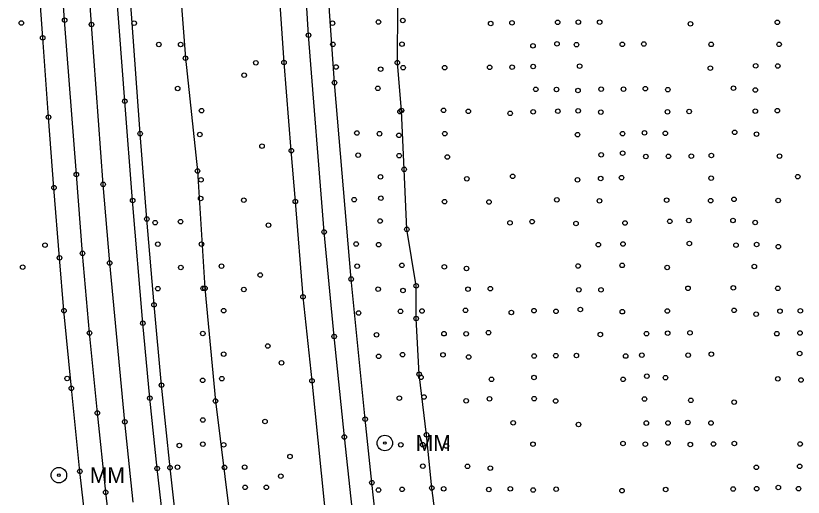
# Model space of a CAD drawing. Extents: x 20503438 to 20508873, y 7964251 to 7984667.
# Drawn here: x 20505414.7 to 20505763.9, y 7977994.1 to 7978207.5 of the extents above; entities that cross this region are included whole.
import ezdxf

# ---------------------------------------------------------------- set-up
doc = ezdxf.new("R2010")
doc.units = 0
for name, color, linetype in [('SurBreakLine', 7, 'Continuous'), ('SurDrainageArrowUp', 7, 'Continuous'), ('SurEdgeRoadPaved', 7, 'Continuous'), ('SurEdgeShoulderPaved', 7, 'Continuous'), ('SurRoadPoints', 7, 'Continuous'), ('SurSurveyPoints', 7, 'Continuous')]:
    doc.layers.add(name, color=color, linetype=linetype)

msp = doc.modelspace()

# ---------------------------------------------------------------- linework, layer by layer
at = {"layer": 'SurBreakLine'}
for points in [[(20505552.87, 7977978.47), (20505546.05, 7978045.7), (20505542.06, 7978082.94), (20505538.66, 7978125.24), (20505536.87, 7978147.75), (20505533.64, 7978186.84), (20505531.3, 7978221.22), (20505529.21, 7978255.03), (20505525.72, 7978323.37), (20505522.4, 7978394.4), (20505521.1, 7978429.03), (20505519.75, 7978458.72), (20505518.73, 7978501.89), (20505518.06, 7978531.07), (20505517.2, 7978583.22), (20505516.23, 7978653.48), (20505516.64, 7978710.22), (20505516.01, 7978735.22), (20505514.78, 7978760.21), (20505514.35, 7978785.2), (20505514.46, 7978817.7)], [(20505466.7, 7977991.92), (20505463.05, 7978027.55), (20505456.33, 7978097.95), (20505453.46, 7978132.8), (20505448.25, 7978203.68), (20505445.78, 7978239.4), (20505443.04, 7978273.69), (20505437.22, 7978404.79), (20505435.97, 7978443.35), (20505435.15, 7978478.03), (20505432.45, 7978640.01), (20505431.71, 7978709.45), (20505431.58, 7978734.45), (20505430.86, 7978759.44), (20505430.93, 7978784.44), (20505430.5, 7978796.56)]]:
    msp.add_lwpolyline(points, dxfattribs=at)
at = {"layer": 'SurDrainageArrowUp'}
for points in [[(20505602.24, 7977974.48), (20505599.16, 7977998.23), (20505596.82, 7978021.77), (20505593.55, 7978048.65), (20505592.23, 7978073.31), (20505592.27, 7978087.79), (20505588.1, 7978112.9), (20505586.91, 7978139.46), (20505585.7, 7978165.54), (20505583.91, 7978186.74), (20505584.15, 7978212.07), (20505581.05, 7978236.78), (20505581.32, 7978280.92), (20505580.84, 7978306.07), (20505580.17, 7978331.58), (20505581.09, 7978356.03), (20505579.49, 7978380.22), (20505579.69, 7978403.05), (20505578.72, 7978427.74)], [(20505474.88, 7978262.46), (20505478.99, 7978261.36), (20505482.21, 7978256.52), (20505486.17, 7978242.38), (20505487.91, 7978215.78), (20505489.93, 7978188.71), (20505495.31, 7978138.74), (20505498.58, 7978086.73), (20505503.22, 7978036.77), (20505509.44, 7977986.63), (20505514.32, 7977937.98), (20505520.92, 7977890), (20505527.82, 7977841.73), (20505542.62, 7977744.41), (20505553.31, 7977670.21)]]:
    msp.add_lwpolyline(points, dxfattribs=at)
at = {"layer": 'SurEdgeRoadPaved'}
for points in [[(20505566.3, 7977965.9), (20505560.41, 7978020.83), (20505555.87, 7978065.38), (20505551.42, 7978111.71), (20505544.52, 7978198.95), (20505542.7, 7978228.03), (20505541.09, 7978258.93), (20505537.75, 7978313.23), (20505535.28, 7978370.22), (20505534.58, 7978398.47), (20505532.2, 7978452.12), (20505531.93, 7978463.46), (20505530.96, 7978505.02), (20505530.55, 7978531.59), (20505528.81, 7978607.5), (20505527.04, 7978710.32), (20505526.81, 7978735.32), (20505526.38, 7978760.31), (20505526.15, 7978785.31), (20505524.78, 7978963.79)], [(20505463.18, 7977920.65), (20505454.58, 7977996.31), (20505450.89, 7978031.46), (20505447.41, 7978066.92), (20505444.29, 7978102.21), (20505441.55, 7978137.15), (20505436.35, 7978205.55), (20505433.64, 7978243.47), (20505431.53, 7978275.3), (20505426.62, 7978379.16), (20505424.19, 7978443.31), (20505423.37, 7978477.17), (20505421.86, 7978573.74), (20505421.02, 7978610.89), (20505420.15, 7978671.98), (20505420.51, 7978709.3), (20505420.18, 7978734.3), (20505419.46, 7978759.29), (20505419.53, 7978784.3), (20505418.19, 7978836.37)], [(20505484.78, 7977942.17), (20505477.37, 7978006.84), (20505474.16, 7978038.05), (20505471.02, 7978071.25), (20505466.52, 7978125.62), (20505463.03, 7978169.65), (20505458.22, 7978233.87), (20505456.38, 7978261.7), (20505452.65, 7978331.42), (20505449.66, 7978395.61), (20505448.48, 7978428.35), (20505447.47, 7978464.74), (20505446.76, 7978498.61), (20505444.84, 7978603.27), (20505443.98, 7978671.39), (20505443.11, 7978709.6), (20505442.78, 7978734.59), (20505442.86, 7978759.6), (20505442.33, 7978784.59), (20505442.48, 7978812.32)]]:
    msp.add_lwpolyline(points, dxfattribs=at)
at = {"layer": 'SurEdgeShoulderPaved'}
for points in [[(20505576.26, 7977966.69), (20505572.62, 7978000.58), (20505569.66, 7978028.71), (20505563.41, 7978090.82), (20505556.03, 7978177.85), (20505553.77, 7978209.53), (20505550.55, 7978266.31), (20505548.09, 7978306.49), (20505546.4, 7978339.91), (20505545.18, 7978373.07), (20505543.7, 7978404.19), (20505541.19, 7978469.47), (20505540.34, 7978515.04), (20505539.62, 7978564.96), (20505538.97, 7978593.38), (20505538.5, 7978624.24), (20505538.02, 7978682.14), (20505537.78, 7978710.42), (20505537.52, 7978735.42), (20505537.14, 7978760.41), (20505537.01, 7978785.41), (20505536.59, 7978812.4)], [(20505486.93, 7977972.52), (20505483.11, 7978007.2), (20505479.29, 7978043.79), (20505475.99, 7978079.42), (20505472.82, 7978117.44), (20505469.87, 7978155.29), (20505462.19, 7978261.58), (20505458.76, 7978328.16), (20505455.59, 7978394), (20505454.25, 7978428.29), (20505453.33, 7978459.97), (20505451.73, 7978529.85), (20505451.25, 7978561.06), (20505450.65, 7978609.09), (20505449.7, 7978709.68), (20505449.58, 7978734.68), (20505448.86, 7978759.68), (20505448.73, 7978784.68), (20505448.43, 7978797.39)], [(20505450.99, 7977936.46), (20505443.13, 7978005.6), (20505439.35, 7978042.41), (20505436.05, 7978076.83), (20505434.09, 7978100.23), (20505431.61, 7978131.31), (20505429.24, 7978162.59), (20505426.65, 7978197.75), (20505425.16, 7978218.23), (20505422.3, 7978254.13), (20505421.45, 7978269.03), (20505420.26, 7978289.89), (20505414.68, 7978424.62)]]:
    msp.add_lwpolyline(points, dxfattribs=at)
at = {"layer": 'SurRoadPoints'}
for centre, radius in [((20505578.33, 7978018.15), 3.43), ((20505578.33, 7978018.15), 0.571), ((20505433.81, 7978003.9), 3.43), ((20505433.81, 7978003.9), 0.571)]:
    msp.add_circle(centre, radius, dxfattribs=at)
at = {"layer": 'SurSurveyPoints'}
for centre in [(20505436.35, 7978205.55), (20505575.5, 7978204.77), (20505586.3, 7978205.46), (20505654.99, 7978204.61), (20505664.16, 7978204.72), (20505673.62, 7978204.66), (20505752.4, 7978204.63), (20505417.16, 7978204.34), (20505448.25, 7978203.68), (20505467.18, 7978204.24), (20505555.13, 7978204.23), (20505625.31, 7978204.07), (20505634.72, 7978204.39), (20505713.87, 7978203.95), (20505426.65, 7978197.75), (20505544.52, 7978198.95), (20505478.11, 7978194.82), (20505487.81, 7978194.82), (20505555.32, 7978194.87), (20505585.96, 7978194.97), (20505644.07, 7978194.24), (20505654.71, 7978195.09), (20505663.34, 7978194.73), (20505683.63, 7978194.85), (20505693.19, 7978195.01), (20505723.06, 7978194.84), (20505753.19, 7978194.89), (20505489.93, 7978188.71), (20505521.13, 7978186.71), (20505533.64, 7978186.84), (20505556.74, 7978184.84), (20505576.48, 7978183.84), (20505583.91, 7978186.74), (20505586.46, 7978184.5), (20505604.91, 7978184.53), (20505624.85, 7978184.66), (20505634.78, 7978184.74), (20505644.13, 7978185.02), (20505664.71, 7978185.19), (20505722.71, 7978184.3), (20505742.82, 7978185.33), (20505752.58, 7978185.27), (20505515.97, 7978181.19), (20505556.03, 7978177.85), (20505486.51, 7978175.33), (20505575.24, 7978175.4), (20505645.28, 7978174.94), (20505654.48, 7978174.89), (20505664, 7978174.38), (20505674.28, 7978175), (20505684.2, 7978175), (20505693.88, 7978175.25), (20505703.85, 7978174.8), (20505732.93, 7978175.42), (20505742.65, 7978174.6), (20505463.03, 7978169.65), (20505429.24, 7978162.59), (20505497.07, 7978165.5), (20505585.1, 7978165.03), (20505585.7, 7978165.54), (20505604.39, 7978165.62), (20505615.36, 7978165.18), (20505633.93, 7978164.3), (20505644.16, 7978164.95), (20505655.1, 7978165.21), (20505664.06, 7978165.4), (20505674.12, 7978164.84), (20505703.71, 7978164.94), (20505713.29, 7978165.09), (20505742.64, 7978165.28), (20505752.43, 7978165.5), (20505565.95, 7978155.55), (20505693.5, 7978155.62), (20505733.48, 7978155.87), (20505469.87, 7978155.29), (20505496.28, 7978154.87), (20505575.98, 7978155.24), (20505584.59, 7978154.52), (20505604.92, 7978155.27), (20505663.82, 7978154.86), (20505683.76, 7978155.3), (20505702.74, 7978155.4), (20505743.19, 7978155.09), (20505523.91, 7978149.77), (20505536.87, 7978147.75), (20505566.51, 7978145.73), (20505584.71, 7978145.51), (20505674.3, 7978145.91), (20505683.81, 7978146.62), (20505694.08, 7978145.13), (20505704.1, 7978145.25), (20505714.26, 7978145.32), (20505723.16, 7978145.58), (20505753.36, 7978145.34), (20505606.06, 7978144.96), (20505495.31, 7978138.74), (20505586.91, 7978139.46), (20505441.55, 7978137.15), (20505496.8, 7978134.83), (20505576.42, 7978136.12), (20505614.72, 7978135.28), (20505635.02, 7978136.37), (20505663.8, 7978134.82), (20505674.08, 7978135.38), (20505683.32, 7978135.76), (20505723.05, 7978135.56), (20505761.46, 7978136.21), (20505431.61, 7978131.31), (20505453.46, 7978132.8), (20505466.52, 7978125.62), (20505496.65, 7978126.5), (20505515.8, 7978125.8), (20505538.66, 7978125.24), (20505564.73, 7978126.04), (20505576.61, 7978126.66), (20505604.83, 7978125.15), (20505624.54, 7978125.01), (20505654.6, 7978125.96), (20505673.5, 7978125.51), (20505703.32, 7978125.76), (20505722.82, 7978125.58), (20505733.15, 7978126.15), (20505752.79, 7978125.65), (20505472.82, 7978117.44), (20505476.52, 7978115.81), (20505487.76, 7978116.25), (20505526.73, 7978114.71), (20505576.25, 7978116.56), (20505633.86, 7978115.77), (20505643.65, 7978116.24), (20505663.1, 7978115.46), (20505684.87, 7978115.67), (20505704.69, 7978116.4), (20505713.14, 7978116.78), (20505732.72, 7978116.82), (20505742.6, 7978115.86), (20505551.42, 7978111.71), (20505588.1, 7978112.9), (20505427.63, 7978105.86), (20505477.67, 7978106.28), (20505497.01, 7978106.32), (20505565.62, 7978106.35), (20505575.58, 7978106.08), (20505673.04, 7978106.1), (20505683.94, 7978106.34), (20505713.4, 7978106.59), (20505734.05, 7978105.85), (20505743.22, 7978106.15), (20505752.85, 7978105.21), (20505434.09, 7978100.23), (20505444.29, 7978102.21), (20505456.33, 7978097.95), (20505505.92, 7978096.56), (20505566.09, 7978096.54), (20505585.91, 7978096.93), (20505604.74, 7978096.25), (20505664.05, 7978096.63), (20505683.58, 7978096.88), (20505742.17, 7978096.42), (20505417.77, 7978096.08), (20505487.86, 7978095.96), (20505614.56, 7978095.54), (20505703.57, 7978095.99), (20505523.09, 7978092.6), (20505563.41, 7978090.82), (20505477.68, 7978086.59), (20505497.75, 7978086.73), (20505498.58, 7978086.73), (20505515.82, 7978086.21), (20505575.36, 7978086.36), (20505586.38, 7978085.72), (20505592.27, 7978087.79), (20505615.25, 7978086.32), (20505625.15, 7978086.58), (20505664.38, 7978086.08), (20505674.2, 7978086.07), (20505712.81, 7978086.75), (20505732.87, 7978086.91), (20505752.6, 7978086.72), (20505542.06, 7978082.94), (20505475.99, 7978079.42), (20505436.05, 7978076.83), (20505506.91, 7978076.83), (20505566.69, 7978075.8), (20505585.31, 7978076.51), (20505594.82, 7978076.64), (20505614.13, 7978076.96), (20505634.46, 7978076.04), (20505644.46, 7978076.81), (20505654.28, 7978076.54), (20505665.06, 7978077.35), (20505683.63, 7978076.34), (20505703.64, 7978076.7), (20505733.23, 7978076.95), (20505743.02, 7978075.25), (20505753.56, 7978076.56), (20505762.6, 7978076.74), (20505592.23, 7978073.31), (20505471.02, 7978071.25), (20505447.41, 7978066.92), (20505497.62, 7978066.7), (20505555.87, 7978065.38), (20505574.69, 7978066.14), (20505604.59, 7978066.59), (20505614.43, 7978066.54), (20505624.33, 7978067.08), (20505673.91, 7978066.22), (20505694.39, 7978066.64), (20505703.79, 7978066.82), (20505713.68, 7978066.98), (20505752.18, 7978066.59), (20505762.42, 7978066.93), (20505526.44, 7978061.13), (20505762.31, 7978057.82), (20505506.88, 7978057.57), (20505575.6, 7978056.57), (20505586.21, 7978057.34), (20505604.14, 7978057.22), (20505615.54, 7978056.31), (20505644.58, 7978056.72), (20505654.17, 7978056.87), (20505663.3, 7978056.92), (20505685.15, 7978056.69), (20505692.31, 7978057.11), (20505712.87, 7978057.11), (20505723.1, 7978057.51), (20505532.51, 7978053.69), (20505593.55, 7978048.65), (20505694.53, 7978047.77), (20505437.48, 7978046.75), (20505497.56, 7978045.94), (20505506.05, 7978046.67), (20505546.05, 7978045.7), (20505594.41, 7978047.28), (20505625.63, 7978046.41), (20505644.5, 7978047.16), (20505684.01, 7978046.35), (20505702.82, 7978047.12), (20505752.61, 7978046.58), (20505762.89, 7978046.09), (20505439.35, 7978042.41), (20505479.29, 7978043.79), (20505474.16, 7978038.05), (20505584.8, 7978038.03), (20505595.72, 7978038.54), (20505614.41, 7978036.85), (20505624.77, 7978037.72), (20505644.57, 7978037.78), (20505693.51, 7978037.64), (20505714.02, 7978037.09), (20505503.22, 7978036.77), (20505654.08, 7978036.8), (20505733.25, 7978036.29), (20505450.89, 7978031.46), (20505463.05, 7978027.55), (20505497.66, 7978028.37), (20505525.21, 7978027.69), (20505569.66, 7978028.71), (20505635.29, 7978027.09), (20505664.26, 7978026.36), (20505694.3, 7978026.99), (20505703.91, 7978027.03), (20505712.69, 7978027.27), (20505722.95, 7978027.03), (20505560.41, 7978020.83), (20505596.82, 7978021.77), (20505487.23, 7978017.02), (20505497.63, 7978017.66), (20505506.87, 7978017.33), (20505585.42, 7978017.37), (20505595.13, 7978017.43), (20505605.59, 7978016.83), (20505644.05, 7978017.62), (20505683.96, 7978017.92), (20505693.88, 7978017.66), (20505703.94, 7978018.16), (20505713.79, 7978017.46), (20505724.06, 7978017.74), (20505733.36, 7978017.94), (20505762.5, 7978017.73), (20505536.28, 7978012.14), (20505443.13, 7978005.6), (20505477.37, 7978006.84), (20505483.11, 7978007.2), (20505486.38, 7978007.46), (20505507.21, 7978007.34), (20505516.19, 7978007.47), (20505595.19, 7978007.91), (20505615.01, 7978007.84), (20505625.11, 7978007.03), (20505743.08, 7978007.39), (20505762.31, 7978007.81), (20505532.2, 7978003.45), (20505516.39, 7977998.49), (20505525.82, 7977998.5), (20505572.62, 7978000.58), (20505752.83, 7977998.42), (20505454.58, 7977996.31), (20505575.54, 7977997.3), (20505586.01, 7977997.64), (20505599.16, 7977998.23), (20505604.46, 7977997.88), (20505624.47, 7977997.51), (20505633.98, 7977997.87), (20505644.14, 7977997.32), (20505654.33, 7977997.67), (20505683.55, 7977997.02), (20505702.91, 7977997.51), (20505732.83, 7977997.75), (20505743.21, 7977997.91), (20505761.81, 7977997.92)]:
    msp.add_circle(centre, 1, dxfattribs=at)

# ---------------------------------------------------------------- texts
at = {"layer": 'SurRoadPoints'}
for p in [(20505592.04, 7978014.65), (20505447.52, 7978000.4)]:
    msp.add_text('MM', height=6.995, rotation=360, dxfattribs=at).set_placement(p)

doc.saveas('drawing.dxf')
